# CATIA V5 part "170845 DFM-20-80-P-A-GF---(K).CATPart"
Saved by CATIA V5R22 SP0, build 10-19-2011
Part number: 170845 DFM-20-80-P-A-GF---(K)
Property "ParasolidId": 6
Property "PSOL_INSTNR": 2
Bounding box of the stored display mesh (mm): x -147 to 14, y -16 to 18, z -40.5 to 40.5
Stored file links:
  U:\S9A\PER\CAO\Assemblage\Cadre\Chariot_Y\Prehenseur\170845 DFM-20-80-P-A-GF---(K).CATPart
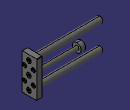
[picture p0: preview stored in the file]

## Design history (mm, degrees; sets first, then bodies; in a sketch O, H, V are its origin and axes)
Body1 "170845 DFM-20-80-P-A-GF---(K)" (main body)
  Solid1: solid without history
